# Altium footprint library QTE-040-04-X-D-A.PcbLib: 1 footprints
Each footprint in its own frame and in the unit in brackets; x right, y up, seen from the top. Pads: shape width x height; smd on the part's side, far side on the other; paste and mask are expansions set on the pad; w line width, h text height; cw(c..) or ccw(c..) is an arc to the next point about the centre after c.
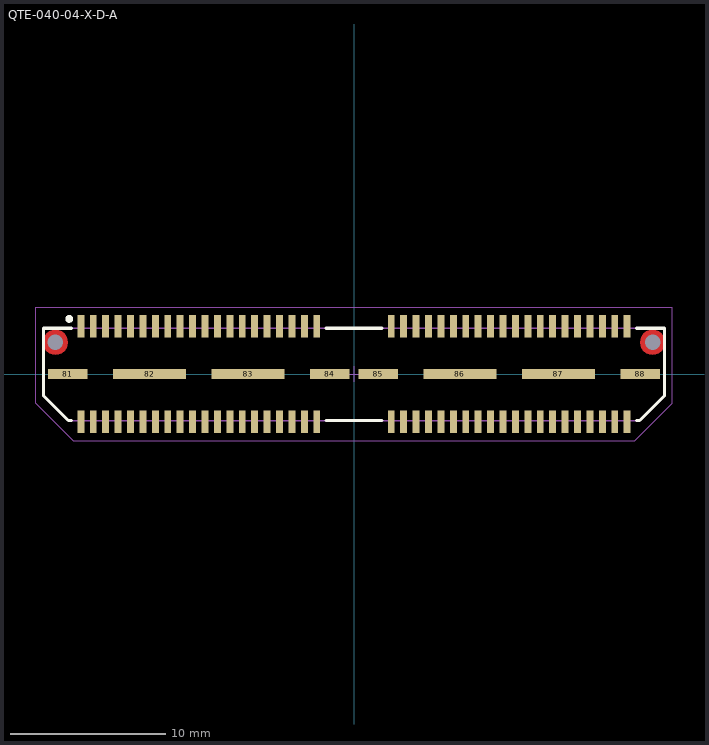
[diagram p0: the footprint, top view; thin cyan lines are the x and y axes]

## QTE-040-04-X-D-A [mm] "0.50mm pitch, 80 pin, high speed terminal strip"
height 4.27
pads (90):
  rect 0.45x1.45 smd mask+0: 1(-17.6,3.09) 2(-17.6,-3.09) 3(-16.8,3.09) 4(-16.8,-3.09) 5(-16,3.09) 6(-16,-3.09) 7(-15.2,3.09) 8(-15.2,-3.09) 9(-14.4,3.09) 10(-14.4,-3.09) 11(-13.6,3.09) 12(-13.6,-3.09) 13(-12.8,3.09) 14(-12.8,-3.09) 15(-12,3.09) 16(-12,-3.09) 17(-11.2,3.09) 18(-11.2,-3.09) 19(-10.4,3.09) 20(-10.4,-3.09) 21(-9.6,3.09) 22(-9.6,-3.09) 23(-8.8,3.09) 24(-8.8,-3.09) 25(-8,3.09) 26(-8,-3.09) 27(-7.2,3.09) 28(-7.2,-3.09) 29(-6.4,3.09) 30(-6.4,-3.09) 31(-5.6,3.09) 32(-5.6,-3.09) 33(-4.8,3.09) 34(-4.8,-3.09) 35(-4,3.09) 36(-4,-3.09) 37(-3.2,3.09) 38(-3.2,-3.09) 39(-2.4,3.09) 40(-2.4,-3.09) 41(2.4,3.09) 42(2.4,-3.09) 43(3.2,3.09) 44(3.2,-3.09) 45(4,3.09) 46(4,-3.09) 47(4.8,3.09) 48(4.8,-3.09) 49(5.6,3.09) 50(5.6,-3.09) 51(6.4,3.09) 52(6.4,-3.09) 53(7.2,3.09) 54(7.2,-3.09) 55(8,3.09) 56(8,-3.09) 57(8.8,3.09) 58(8.8,-3.09) 59(9.6,3.09) 60(9.6,-3.09) 61(10.4,3.09) 62(10.4,-3.09) 63(11.2,3.09) 64(11.2,-3.09) 65(12,3.09) 66(12,-3.09) 67(12.8,3.09) 68(12.8,-3.09) 69(13.6,3.09) 70(13.6,-3.09) 71(14.4,3.09) 72(14.4,-3.09) 73(15.2,3.09) 74(15.2,-3.09) 75(16,3.09) 76(16,-3.09) 77(16.8,3.09) 78(16.8,-3.09) 79(17.6,3.09) 80(17.6,-3.09)
  rect 2.55x0.65 smd mask+0: 81(-18.445,0) 84(-1.555,0) 85(1.555,0) 88(18.445,0)
  rect 4.7x0.65 smd mask+0: 82(-13.175,0) 83(-6.825,0) 86(6.825,0) 87(13.175,0)
  round 0.5 hole 1 unplated mask+0: 89(-19.24,2.04) 90(19.24,2.04)
Top Layer:
  pour cut-out: 20.047,2.04 20.019,2.249 19.939,2.443 19.811,2.611 19.643,2.739 19.449,2.819 19.24,2.847 19.031,2.819 18.837,2.739 18.669,2.611 18.541,2.443 18.461,2.249 18.433,2.04 18.461,1.831 18.541,1.637 18.669,1.469 18.837,1.341 19.031,1.261 19.24,1.233 19.449,1.261 19.643,1.341 19.811,1.469 19.939,1.637 20.019,1.831
  pour cut-out: -18.433,2.04 -18.461,2.249 -18.541,2.443 -18.669,2.611 -18.837,2.739 -19.031,2.819 -19.24,2.847 -19.449,2.819 -19.643,2.739 -19.811,2.611 -19.939,2.443 -20.019,2.249 -20.047,2.04 -20.019,1.831 -19.939,1.637 -19.811,1.469 -19.643,1.341 -19.449,1.261 -19.24,1.233 -19.031,1.261 -18.837,1.341 -18.669,1.469 -18.541,1.637 -18.461,1.831
Top Overlay:
  circle w0.25: c-18.35,3.55 r0.125
  lines w0.2: -18.2,-3 -18.4,-3 -20,-1.4 -20,2.95 -18.2,2.95 ; -1.8,-3 1.8,-3 ; -1.8,2.95 1.8,2.95 ; 18.2,-3 18.4,-3 20,-1.4 20,2.95 18.2,2.95
Mechanical 13:
  lines w0.01: -20,-1.4 -20,2.95 20,2.95 20,-1.4 18.4,-3 -18.4,-3 -20,-1.4
  lines w0.1: -20,-1.4 -20,2.95 20,2.95 20,-1.4 18.4,-3 -18.4,-3 -20,-1.4
  text ".Designator" at 0.254,0.254 h1.52
Mechanical 15:
  lines w0.05: -0.5,0 0.5,0 ; 0,-0.5 0,0.5 ; -20.5,-1.9 -20.5,4.3 20.5,4.3 20.5,-1.9 18.1,-4.3 -18.1,-4.3 -20.5,-1.9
